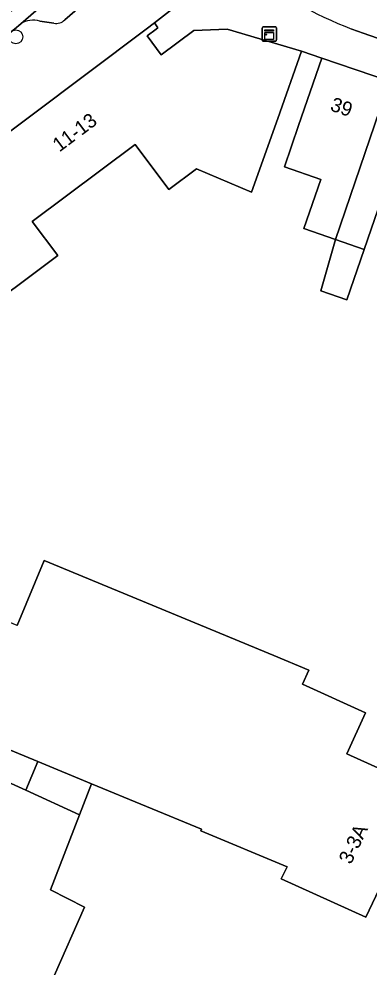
# Model space of a CAD drawing. Extents: x 160023 to 161302, y 384750 to 385707.
# Drawn here: x 160607.5 to 160632.1, y 385184.2 to 385250.7 of the extents above; entities that cross this region are included whole.
import ezdxf

# ---------------------------------------------------------------- set-up
doc = ezdxf.new("R2010")
doc.units = 0
for name, color, linetype in [('IMGEO_Boom', 7, 'Continuous'), ('IMGEO_Erf', 7, 'Continuous'), ('IMGEO_Kast', 7, 'Continuous'), ('IMGEO_Pand', 7, 'Continuous'), ('IMGEO_Pand_nummerreeks', 7, 'Continuous'), ('IMGEO_Parkeervlak_open', 7, 'Continuous'), ('IMGEO_Rijbaan_lokaal_open', 7, 'Continuous'), ('IMGEO_Voetpad_open', 7, 'Continuous')]:
    doc.layers.add(name, color=color, linetype=linetype)

msp = doc.modelspace()

# ---------------------------------------------------------------- linework, layer by layer
at = {"layer": 'IMGEO_Boom'}
msp.add_circle((160607.298, 385249.454), 0.489, dxfattribs=at)
at = {"layer": 'IMGEO_Erf'}
for points in [[(160632.949, 385238.074), (160631.734, 385234.552), (160630.516, 385231.022), (160628.689, 385231.653), (160629.723, 385235.245), (160627.508, 385236.009), (160628.699, 385239.462), (160626.136, 385240.346), (160627.132, 385243.232), (160628.762, 385247.958), (160627.349, 385248.446), (160625.671, 385243.736), (160623.828, 385238.566), (160619.984, 385240.212), (160618.04, 385238.756), (160615.674, 385241.915), (160608.451, 385236.506), (160610.234, 385234.126), (160604.075, 385229.515)], [(160607.402, 385208.178), (160609.289, 385212.738), (160625.401, 385206.073), (160627.847, 385205.061), (160627.4, 385204.071), (160631.823, 385202.07), (160630.518, 385199.185), (160636.108, 385196.657), (160631.865, 385187.739), (160625.909, 385190.433), (160626.334, 385191.264), (160620.278, 385193.789), (160620.324, 385193.9), (160612.612, 385197.091), (160611.769, 385194.919), (160609.727, 385189.658), (160612.123, 385188.445), (160607.868, 385178.798)], [(160603.295, 385198.77), (160608.005, 385196.629), (160608.842, 385198.651), (160604.478, 385200.456)]]:
    msp.add_lwpolyline(points, dxfattribs=at)
at = {"layer": 'IMGEO_Kast'}
for p, q in [((160624.582, 385249.228), (160624.582, 385250.069)), ((160624.582, 385250.069), (160624.582, 385249.228)), ((160624.657, 385250.153), (160625.498, 385250.153)), ((160625.498, 385250.153), (160624.657, 385250.153)), ((160625.582, 385250.078), (160625.582, 385249.237)), ((160625.582, 385249.237), (160625.582, 385250.078)), ((160625.507, 385249.153), (160624.666, 385249.153)), ((160624.666, 385249.153), (160625.507, 385249.153))]:
    msp.add_line(p, q, dxfattribs=at)
for points in [[(160624.777, 385249.943), (160625.377, 385249.943), (160625.377, 385249.858), (160624.777, 385249.858), (160624.777, 385249.943)], [(160624.777, 385249.768), (160625.377, 385249.768), (160625.377, 385249.279), (160624.777, 385249.279), (160624.777, 385249.768)]]:
    msp.add_lwpolyline(points, dxfattribs=at)
msp.add_circle((160624.861, 385249.617), 0.0377, dxfattribs=at)
for centre, start, end in [((160624.66, 385250.075), 92.4484, 184.28452), ((160624.66, 385250.075), 92.4484, 184.28452), ((160625.504, 385250.075), 2.4484, 94.28452), ((160625.504, 385250.075), 2.4484, 94.28452), ((160624.66, 385249.231), 182.4484, 274.28452), ((160624.66, 385249.231), 182.4484, 274.28452), ((160625.504, 385249.231), 272.4484, 4.28452), ((160625.504, 385249.231), 272.4484, 4.28452)]:
    msp.add_arc(centre, 0.0779, start, end, dxfattribs=at)
at = {"layer": 'IMGEO_Pand'}
msp.add_lwpolyline([(160604.075, 385229.515), (160610.234, 385234.126), (160608.451, 385236.506), (160615.674, 385241.915), (160618.04, 385238.756), (160619.984, 385240.212), (160623.828, 385238.566), (160625.671, 385243.736), (160627.349, 385248.446), (160622.129, 385250), (160619.789, 385249.898), (160617.504, 385248.187), (160616.505, 385249.522), (160617.144, 385250), (160617.271, 385250.095), (160617.017, 385250.434), (160616.437, 385250), (160604.177, 385240.819)], dxfattribs=at)
for points in [[(160628.762, 385247.958), (160627.132, 385243.232), (160626.136, 385240.346), (160628.699, 385239.462), (160627.508, 385236.009), (160629.723, 385235.245), (160633.505, 385246.342)], [(160633.505, 385246.342), (160629.723, 385235.245), (160631.734, 385234.552), (160632.949, 385238.074), (160635.637, 385237.146), (160636.621, 385239.999), (160638.251, 385244.725)], [(160631.734, 385234.552), (160629.723, 385235.245), (160628.689, 385231.653), (160630.516, 385231.022)], [(160631.823, 385202.07), (160627.4, 385204.071), (160627.847, 385205.061), (160625.401, 385206.073), (160609.289, 385212.738), (160607.402, 385208.178), (160603.417, 385209.826), (160600.672, 385203.19), (160604.478, 385200.456), (160608.842, 385198.651), (160612.612, 385197.091), (160620.324, 385193.9), (160620.278, 385193.789), (160626.334, 385191.264), (160625.909, 385190.433), (160631.865, 385187.739), (160636.108, 385196.657), (160630.518, 385199.185)], [(160612.123, 385188.445), (160609.727, 385189.658), (160611.769, 385194.919), (160608.005, 385196.629), (160603.295, 385198.77), (160596.337, 385182.087), (160607.868, 385178.798)], [(160612.612, 385197.091), (160608.842, 385198.651), (160608.005, 385196.629), (160611.769, 385194.919)]]:
    msp.add_lwpolyline(points, close=True, dxfattribs=at)
at = {"layer": 'IMGEO_Parkeervlak_open'}
for points in [[(160616.093, 385257.714), (160615.561, 385257.252), (160607.648, 385250.361)], [(160610.726, 385250.64), (160615.241, 385254.575)], [(160608.978, 385250.561), (160609.97, 385250.406)], [(160630.881, 385250), (160631.668, 385249.714), (160639.654, 385246.93), (160644.488, 385245.245), (160659.581, 385239.998), (160663.384, 385238.688), (160676.625, 385234.092), (160681.528, 385232.39), (160708.023, 385223.237), (160712.287, 385221.77), (160781.115, 385197.893), (160781.566, 385199.169)]]:
    msp.add_lwpolyline(points, dxfattribs=at)
for centre, radius, start, end in [((160640.292, 385274.681), 26.415, 230.51448, 249.12905), ((160608.522, 385249.073), 1.557, 72.95857, 124.14509), ((160610.105, 385251.31), 0.914, 261.53277, 312.86431)]:
    msp.add_arc(centre, radius, start, end, dxfattribs=at)
at = {"layer": 'IMGEO_Rijbaan_lokaal_open'}
msp.add_lwpolyline([(160592.613, 385237.855), (160594.09, 385239.101), (160594.86, 385239.729), (160595.998, 385240.634), (160604.501, 385247.635), (160606.547, 385249.472), (160607.197, 385250), (160607.648, 385250.361), (160615.561, 385257.252), (160614.832, 385258.169), (160605.517, 385250), (160605.294, 385249.81), (160596.334, 385242.394)], dxfattribs=at)
at = {"layer": 'IMGEO_Voetpad_open'}
for points in [[(160616.437, 385250), (160617.017, 385250.434), (160624.198, 385256.053), (160622.539, 385257.222), (160621.764, 385257.768)], [(160624.198, 385256.053), (160617.017, 385250.434), (160617.271, 385250.095), (160617.144, 385250), (160616.505, 385249.522), (160617.504, 385248.187), (160619.789, 385249.898), (160622.129, 385250), (160627.349, 385248.446), (160628.762, 385247.958), (160633.505, 385246.342), (160638.251, 385244.725), (160639.183, 385244.368), (160649.749, 385240.684), (160649.954, 385240.612), (160650.355, 385241.86), (160655.108, 385240.127), (160659.699, 385238.453), (160661.59, 385237.763), (160667.39, 385235.638), (160672.292, 385233.841), (160676.673, 385232.236), (160679.672, 385231.188)], [(160615.241, 385254.575), (160610.726, 385250.64)], [(160607.648, 385250.361), (160607.197, 385250), (160606.547, 385249.472)], [(160609.97, 385250.406), (160608.978, 385250.561)], [(160604.177, 385240.819), (160616.437, 385250)], [(160712.287, 385221.77), (160711.949, 385220.787), (160707.685, 385222.255), (160708.023, 385223.237), (160681.528, 385232.39), (160681.187, 385231.408), (160676.284, 385233.11), (160676.625, 385234.092), (160663.384, 385238.688), (160663.046, 385237.705), (160659.246, 385239.015), (160659.581, 385239.998), (160644.488, 385245.245), (160644.146, 385244.263), (160639.312, 385245.949), (160639.654, 385246.93), (160631.668, 385249.714), (160630.881, 385250)]]:
    msp.add_lwpolyline(points, dxfattribs=at)
for centre, radius, start, end in [((160640.292, 385274.681), 26.415, 230.51448, 249.12905), ((160608.522, 385249.073), 1.557, 72.95857, 124.14509), ((160610.105, 385251.31), 0.914, 261.53277, 312.86431)]:
    msp.add_arc(centre, radius, start, end, dxfattribs=at)

# ---------------------------------------------------------------- texts
at = {"layer": 'IMGEO_Pand_nummerreeks'}
for s, rotation, p in [('39', 341.18549, (160629.294, 385244.312)), ('11-13', 36.828, (160610.35, 385241.344)), ('3-3A', 64.55515, (160630.808, 385191.382))]:
    msp.add_text(s, height=1, rotation=rotation, dxfattribs=at).set_placement(p)

doc.saveas('drawing.dxf')
